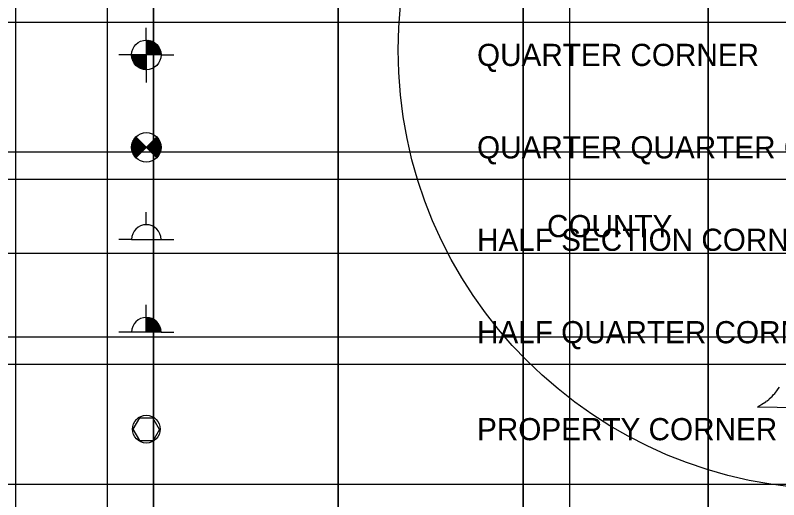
# Model space of a CAD drawing. Extents: x 2146475 to 2147951, y 2147003 to 2148003.
# Drawn here: x 2147543.5 to 2147708.6, y 2147707.7 to 2147812.5 of the extents above; entities that cross this region are included whole.
import ezdxf

# ---------------------------------------------------------------- set-up
doc = ezdxf.new("R2010")
doc.units = 0
for name, color, linetype in [('Bndry_Gov_Ex_Cor_Mon_Quarter_GS', 7, 'Continuous'), ('Bndry_Gov_Ex_Cor_Mon_Section_GS', 7, 'Continuous'), ('Bndry_Gov_Ex_Cor_Mon_Sixteenth_GS', 7, 'Continuous'), ('Bndry_Plat_Ex_Cor_Mon_GS', 7, 'Continuous'), ('Sheet_Border_Line_Wt2', 7, 'Continuous'), ('Sheet_Border_Prof3_Grid+Sta+EL_04_040+08_080', 7, 'Continuous'), ('Sheet_Border_Prof3_Grid+Sta+EL_10_100+20_200', 7, 'Continuous'), ('Sheet_Border_TitleSheet', 7, 'Continuous'), ('Sheet_Border_XS_Grid', 7, 'Continuous'), ('Sheet_Label_Misc_Wt1', 7, 'Continuous')]:
    doc.layers.add(name, color=color, linetype=linetype)

msp = doc.modelspace()

# ---------------------------------------------------------------- linework, layer by layer
at = {"layer": 'Bndry_Gov_Ex_Cor_Mon_Quarter_GS'}
for p, q in [((2147571.89, 2147807.13), (2147571.89, 2147809.82)), ((2147571.89, 2147807.13), (2147571.89, 2147800.73)), ((2147575.09, 2147803.99), (2147571.95, 2147807.13)), ((2147575.08, 2147804.16), (2147572.12, 2147807.13)), ((2147575.07, 2147804.34), (2147572.3, 2147807.11)), ((2147574.99, 2147803.93), (2147571.89, 2147807.03)), ((2147574.83, 2147803.93), (2147571.89, 2147806.87)), ((2147574.67, 2147803.93), (2147571.89, 2147806.71)), ((2147574.51, 2147803.93), (2147571.89, 2147806.55)), ((2147574.34, 2147803.93), (2147571.89, 2147806.39)), ((2147574.18, 2147803.93), (2147571.89, 2147806.22)), ((2147574.02, 2147803.93), (2147571.89, 2147806.06)), ((2147573.86, 2147803.93), (2147571.89, 2147805.9)), ((2147573.7, 2147803.93), (2147571.89, 2147805.74)), ((2147573.54, 2147803.93), (2147571.89, 2147805.58)), ((2147575.04, 2147804.53), (2147572.49, 2147807.08)), ((2147574.99, 2147804.74), (2147572.7, 2147807.03)), ((2147574.92, 2147804.98), (2147572.93, 2147806.96)), ((2147574.81, 2147805.24), (2147573.2, 2147806.85)), ((2147574.63, 2147805.58), (2147573.54, 2147806.68)), ((2147568.69, 2147803.93), (2147565.94, 2147803.93)), ((2147575.09, 2147803.93), (2147568.69, 2147803.93)), ((2147571.89, 2147800.73), (2147568.69, 2147803.93)), ((2147571.89, 2147800.89), (2147568.84, 2147803.93)), ((2147571.89, 2147801.05), (2147569.01, 2147803.93)), ((2147571.89, 2147801.21), (2147569.17, 2147803.93)), ((2147571.89, 2147801.37), (2147569.33, 2147803.93)), ((2147571.89, 2147801.53), (2147569.49, 2147803.93)), ((2147571.89, 2147801.7), (2147569.65, 2147803.93)), ((2147571.89, 2147801.86), (2147569.82, 2147803.93)), ((2147571.89, 2147802.02), (2147569.98, 2147803.93)), ((2147571.89, 2147802.18), (2147570.14, 2147803.93)), ((2147571.89, 2147802.34), (2147570.3, 2147803.93)), ((2147571.89, 2147802.5), (2147570.46, 2147803.93)), ((2147571.9, 2147802.65), (2147570.61, 2147803.94)), ((2147571.89, 2147802.83), (2147570.79, 2147803.93)), ((2147571.89, 2147802.99), (2147570.95, 2147803.93)), ((2147571.89, 2147803.15), (2147571.11, 2147803.93)), ((2147571.89, 2147803.31), (2147571.27, 2147803.93)), ((2147571.89, 2147803.47), (2147571.43, 2147803.93)), ((2147571.89, 2147803.64), (2147571.59, 2147803.93)), ((2147571.89, 2147803.8), (2147571.76, 2147803.93)), ((2147573.37, 2147803.93), (2147571.89, 2147805.42)), ((2147573.21, 2147803.93), (2147571.89, 2147805.25)), ((2147573.05, 2147803.93), (2147571.89, 2147805.09)), ((2147572.89, 2147803.93), (2147571.89, 2147804.93)), ((2147572.73, 2147803.93), (2147571.89, 2147804.77)), ((2147572.56, 2147803.93), (2147571.89, 2147804.61)), ((2147572.4, 2147803.93), (2147571.89, 2147804.45)), ((2147572.24, 2147803.93), (2147571.89, 2147804.28)), ((2147572.08, 2147803.93), (2147571.89, 2147804.12)), ((2147571.92, 2147803.93), (2147571.89, 2147803.96)), ((2147571.89, 2147803.93), (2147571.89, 2147803.93)), ((2147571.89, 2147803.93), (2147571.89, 2147803.93)), ((2147575.09, 2147803.94), (2147575.09, 2147803.93)), ((2147575.09, 2147803.93), (2147577.84, 2147803.93)), ((2147571.72, 2147800.73), (2147568.69, 2147803.76)), ((2147571.54, 2147800.75), (2147568.71, 2147803.58)), ((2147571.36, 2147800.77), (2147568.73, 2147803.4)), ((2147571.15, 2147800.82), (2147568.77, 2147803.19)), ((2147570.93, 2147800.88), (2147568.84, 2147802.97)), ((2147570.68, 2147800.97), (2147568.93, 2147802.72)), ((2147570.37, 2147801.11), (2147569.07, 2147802.41)), ((2147571.89, 2147800.73), (2147571.89, 2147797.98)), ((2147571.89, 2147743.93), (2147571.89, 2147749.82)), ((2147574.99, 2147743.93), (2147571.89, 2147747.03)), ((2147574.83, 2147743.93), (2147571.89, 2147746.87)), ((2147574.67, 2147743.93), (2147571.89, 2147746.71)), ((2147574.51, 2147743.93), (2147571.89, 2147746.55)), ((2147574.34, 2147743.93), (2147571.89, 2147746.39)), ((2147574.18, 2147743.93), (2147571.89, 2147746.22)), ((2147574.02, 2147743.93), (2147571.89, 2147746.06)), ((2147575.09, 2147743.99), (2147571.95, 2147747.13)), ((2147575.08, 2147744.16), (2147572.12, 2147747.13)), ((2147575.07, 2147744.34), (2147572.3, 2147747.11)), ((2147575.04, 2147744.53), (2147572.49, 2147747.08)), ((2147574.99, 2147744.74), (2147572.7, 2147747.03)), ((2147574.92, 2147744.98), (2147572.93, 2147746.96)), ((2147574.81, 2147745.24), (2147573.2, 2147746.85)), ((2147574.63, 2147745.58), (2147573.54, 2147746.68)), ((2147573.86, 2147743.93), (2147571.89, 2147745.9)), ((2147573.7, 2147743.93), (2147571.89, 2147745.74)), ((2147573.54, 2147743.93), (2147571.89, 2147745.58)), ((2147573.37, 2147743.93), (2147571.89, 2147745.42)), ((2147573.21, 2147743.93), (2147571.89, 2147745.25)), ((2147573.05, 2147743.93), (2147571.89, 2147745.09)), ((2147572.89, 2147743.93), (2147571.89, 2147744.93)), ((2147572.73, 2147743.93), (2147571.89, 2147744.77)), ((2147572.56, 2147743.93), (2147571.89, 2147744.61)), ((2147572.4, 2147743.93), (2147571.89, 2147744.45)), ((2147568.69, 2147743.93), (2147565.94, 2147743.93)), ((2147575.09, 2147743.93), (2147568.69, 2147743.93)), ((2147572.24, 2147743.93), (2147571.89, 2147744.28)), ((2147572.08, 2147743.93), (2147571.89, 2147744.12)), ((2147571.92, 2147743.93), (2147571.89, 2147743.96)), ((2147571.89, 2147743.93), (2147571.89, 2147743.93)), ((2147571.89, 2147743.93), (2147571.89, 2147743.93)), ((2147575.09, 2147743.94), (2147575.09, 2147743.93)), ((2147575.09, 2147743.93), (2147577.84, 2147743.93))]:
    msp.add_line(p, q, dxfattribs=at)
msp.add_circle((2147571.89, 2147803.93), 3.2, dxfattribs=at)
msp.add_arc((2147571.89, 2147743.93), 3.2, 0, 180, dxfattribs=at)
at = {"layer": 'Bndry_Gov_Ex_Cor_Mon_Section_GS'}
for p, q in [((2147571.89, 2147767.19), (2147571.89, 2147769.88)), ((2147568.69, 2147763.99), (2147565.94, 2147763.99)), ((2147568.69, 2147763.99), (2147575.09, 2147763.99)), ((2147575.09, 2147764), (2147575.09, 2147763.99)), ((2147575.09, 2147763.99), (2147577.84, 2147763.99))]:
    msp.add_line(p, q, dxfattribs=at)
msp.add_arc((2147571.89, 2147763.99), 3.2, 0, 180, dxfattribs=at)
at = {"layer": 'Bndry_Gov_Ex_Cor_Mon_Sixteenth_GS'}
for p, q in [((2147569.18, 2147782.22), (2147569.18, 2147785.65)), ((2147569.3, 2147782.05), (2147569.3, 2147785.81)), ((2147569.41, 2147781.9), (2147569.41, 2147785.96)), ((2147569.53, 2147781.77), (2147569.53, 2147786.09)), ((2147569.63, 2147781.67), (2147574.15, 2147786.2)), ((2147569.63, 2147786.2), (2147574.15, 2147781.67)), ((2147569.64, 2147781.68), (2147569.64, 2147786.18)), ((2147569.76, 2147781.8), (2147569.76, 2147786.07)), ((2147569.87, 2147781.91), (2147569.87, 2147785.95)), ((2147569.99, 2147782.03), (2147569.99, 2147785.84)), ((2147570.1, 2147782.14), (2147570.1, 2147785.72)), ((2147573.64, 2147782.18), (2147573.64, 2147785.69)), ((2147573.76, 2147782.06), (2147573.76, 2147785.8)), ((2147573.87, 2147781.95), (2147573.87, 2147785.92)), ((2147573.99, 2147781.83), (2147573.99, 2147786.03)), ((2147574.1, 2147781.72), (2147574.1, 2147786.14)), ((2147574.22, 2147781.73), (2147574.22, 2147786.13)), ((2147574.33, 2147781.86), (2147574.33, 2147786)), ((2147574.45, 2147782), (2147574.45, 2147785.86)), ((2147574.56, 2147782.16), (2147574.56, 2147785.7)), ((2147568.84, 2147782.95), (2147568.84, 2147784.91)), ((2147568.96, 2147782.65), (2147568.96, 2147785.21)), ((2147569.07, 2147782.41), (2147569.07, 2147785.45)), ((2147570.21, 2147782.26), (2147570.21, 2147785.61)), ((2147570.33, 2147782.37), (2147570.33, 2147785.49)), ((2147570.44, 2147782.48), (2147570.44, 2147785.38)), ((2147570.56, 2147782.6), (2147570.56, 2147785.26)), ((2147570.67, 2147782.71), (2147570.67, 2147785.15)), ((2147570.79, 2147782.83), (2147570.79, 2147785.04)), ((2147570.9, 2147782.96), (2147570.9, 2147784.91)), ((2147571.01, 2147783.06), (2147571.01, 2147784.81)), ((2147571.13, 2147783.17), (2147571.13, 2147784.69)), ((2147571.24, 2147783.29), (2147571.24, 2147784.58)), ((2147571.36, 2147783.4), (2147571.36, 2147784.46)), ((2147571.47, 2147783.51), (2147571.47, 2147784.35)), ((2147571.59, 2147783.63), (2147571.59, 2147784.24)), ((2147571.7, 2147783.74), (2147571.7, 2147784.12)), ((2147571.81, 2147783.86), (2147571.81, 2147784.01)), ((2147571.93, 2147783.89), (2147571.93, 2147783.97)), ((2147572.04, 2147783.78), (2147572.04, 2147784.09)), ((2147572.16, 2147783.66), (2147572.16, 2147784.2)), ((2147572.27, 2147783.55), (2147572.27, 2147784.31)), ((2147572.39, 2147783.43), (2147572.39, 2147784.43)), ((2147572.5, 2147783.32), (2147572.5, 2147784.54)), ((2147572.62, 2147783.21), (2147572.62, 2147784.66)), ((2147572.73, 2147783.09), (2147572.73, 2147784.77)), ((2147572.84, 2147782.96), (2147572.84, 2147784.91)), ((2147572.96, 2147782.86), (2147572.96, 2147785)), ((2147573.07, 2147782.75), (2147573.07, 2147785.12)), ((2147573.19, 2147782.63), (2147573.19, 2147785.23)), ((2147573.3, 2147782.52), (2147573.3, 2147785.34)), ((2147573.42, 2147782.41), (2147573.42, 2147785.46)), ((2147573.53, 2147782.29), (2147573.53, 2147785.57)), ((2147574.67, 2147782.35), (2147574.67, 2147785.51)), ((2147574.79, 2147782.57), (2147574.79, 2147785.29)), ((2147574.9, 2147782.85), (2147574.9, 2147785.02)), ((2147575.02, 2147783.24), (2147575.02, 2147784.62)), ((2147571.89, 2147783.93), (2147571.89, 2147783.93))]:
    msp.add_line(p, q, dxfattribs=at)
msp.add_circle((2147571.89, 2147783.93), 3.2, dxfattribs=at)
at = {"layer": 'Bndry_Plat_Ex_Cor_Mon_GS'}
for p, q in [((2147569.07, 2147722.92), (2147570.49, 2147725.39)), ((2147570.49, 2147725.39), (2147573.32, 2147725.39)), ((2147574.76, 2147722.89), (2147573.32, 2147725.39)), ((2147570.46, 2147720.51), (2147569.07, 2147722.92)), ((2147574.76, 2147722.89), (2147573.38, 2147720.51)), ((2147570.46, 2147720.51), (2147573.38, 2147720.51))]:
    msp.add_line(p, q, dxfattribs=at)
msp.add_circle((2147571.89, 2147722.95), 3, dxfattribs=at)
at = {"layer": 'Sheet_Border_Line_Wt2'}
msp.add_line((2147543.69, 2147124.95), (2147543.69, 2147920.95), dxfattribs=at)
at = {"layer": 'Sheet_Border_Prof3_Grid+Sta+EL_04_040+08_080'}
for p, q in [((2147563.41, 2147910.95), (2147563.41, 2147136.95)), ((2147613.41, 2147910.95), (2147613.41, 2147136.95)), ((2147663.41, 2147910.95), (2147663.41, 2147136.95)), ((2147813.41, 2147810.95), (2146613.41, 2147810.95)), ((2147813.41, 2147760.95), (2146613.41, 2147760.95)), ((2147813.41, 2147710.95), (2146613.41, 2147710.95))]:
    msp.add_line(p, q, dxfattribs=at)
at = {"layer": 'Sheet_Border_Prof3_Grid+Sta+EL_10_100+20_200'}
for p, q in [((2147573.41, 2147896.95), (2147573.41, 2147152.95)), ((2147613.41, 2147896.95), (2147613.41, 2147152.95)), ((2147653.41, 2147896.95), (2147653.41, 2147152.95)), ((2147693.41, 2147896.95), (2147693.41, 2147152.95)), ((2147813.41, 2147776.95), (2146613.41, 2147776.95)), ((2147813.41, 2147736.95), (2146613.41, 2147736.95))]:
    msp.add_line(p, q, dxfattribs=at)
at = {"layer": 'Sheet_Border_TitleSheet'}
for points in [[(2147704.98, 2147728.37), (2147705.85, 2147728.84), (2147705.93, 2147728.99), (2147706.16, 2147729.06), (2147706.48, 2147729.34), (2147706.55, 2147729.48), (2147707.01, 2147729.89), (2147707.25, 2147730.03), (2147707.48, 2147730.37), (2147707.8, 2147730.66), (2147708.27, 2147731.21), (2147708.51, 2147731.64), (2147708.83, 2147732)], [(2147704.09, 2147727.7), (2147704.39, 2147727.96), (2147704.58, 2147728.04)], [(2147704.58, 2147728.04), (2147704.98, 2147728.37)], [(2147708.29, 2147727.6), (2147704.09, 2147727.7)], [(2147715.46, 2147727.43), (2147708.29, 2147727.6)]]:
    msp.add_lwpolyline(points, dxfattribs=at)
msp.add_circle((2147721.41, 2147805), 95.07, dxfattribs=at)
at = {"layer": 'Sheet_Border_XS_Grid'}
for p, q in [((2147573.41, 2147142.95), (2147573.41, 2147902.95)), ((2147613.41, 2147142.95), (2147613.41, 2147902.95)), ((2147653.41, 2147142.95), (2147653.41, 2147902.95)), ((2147693.41, 2147142.95), (2147693.41, 2147902.95)), ((2146573.41, 2147782.95), (2147853.41, 2147782.95)), ((2146573.41, 2147742.95), (2147853.41, 2147742.95))]:
    msp.add_line(p, q, dxfattribs=at)

# ---------------------------------------------------------------- texts
at = {"layer": 'Sheet_Border_TitleSheet'}
msp.add_text('COUNTY', height=4.8, dxfattribs=at).set_placement((2147658.54, 2147764.49))
at = {"layer": 'Sheet_Label_Misc_Wt1'}
for s, p in [('QUARTER CORNER', (2147643.41, 2147801.53)), ('QUARTER QUARTER CORNER', (2147643.41, 2147781.53)), ('HALF SECTION CORNER', (2147643.41, 2147761.53)), ('HALF QUARTER CORNER', (2147643.41, 2147741.53)), ('PROPERTY CORNER', (2147643.41, 2147720.55))]:
    msp.add_text(s, height=4.8, dxfattribs=at).set_placement(p)

doc.saveas('drawing.dxf')
